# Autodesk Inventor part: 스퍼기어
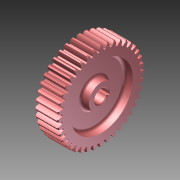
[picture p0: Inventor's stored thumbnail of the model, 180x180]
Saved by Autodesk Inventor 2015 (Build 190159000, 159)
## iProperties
Created: 2024-12
Part Number: 스퍼기어
Material: 일반
Document SubType Name: Modeling
Designer: 102566
Density: 1 g/cm^3
Appearance: 기본값
Author: 102566
Author: jhkim
Creation Date: 2024-11-28
Sending System: Autodesk Inventor 2025
Preprocessor: ST-DEVELOPER v20
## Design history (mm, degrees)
node "스퍼기어1"
node "솔리드1"
node "기준1"
